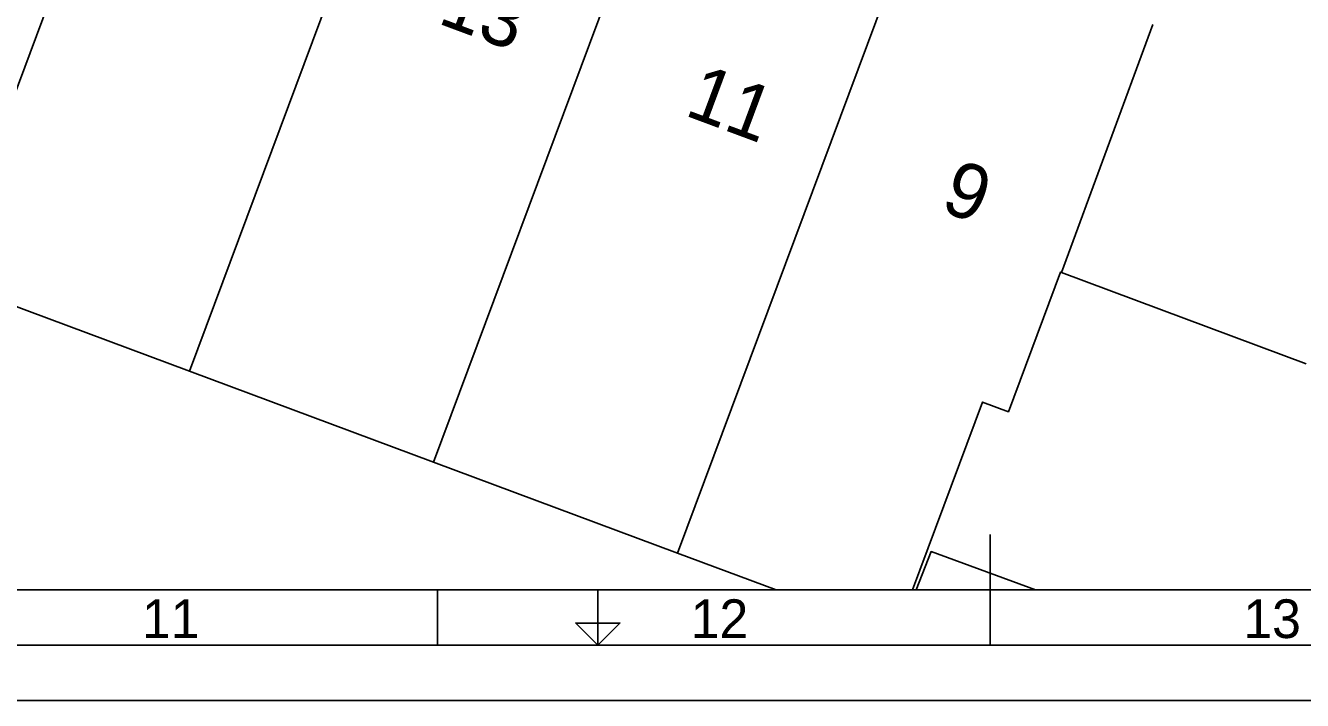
# Model space of a CAD drawing. Extents: x 192672 to 192910, y 446344 to 446512.
# Drawn here: x 192773.19 to 192796.29, y 446343.56 to 446355.77 of the extents above; entities that cross this region are included whole.
import ezdxf

# ---------------------------------------------------------------- set-up
doc = ezdxf.new("R2010")
doc.units = 0
for name, color, linetype in [('1010 viewport', 7, 'Continuous'), ('huisnummerreeks BGT', 7, 'Continuous'), ('pand op maaiveld vlak', 7, 'Continuous'), ('X-XX-AL-TEKENBLAD-S', 7, 'Continuous')]:
    doc.layers.add(name, color=color, linetype=linetype)

msp = doc.modelspace()

# ---------------------------------------------------------------- linework, layer by layer
at = {"layer": '1010 viewport'}
msp.add_lwpolyline([(192675.743, 446509.756), (192860.643, 446509.756), (192860.643, 446345.556), (192675.743, 446345.556)], close=True, dxfattribs=at)
at = {"layer": 'pand op maaiveld vlak'}
for p, q in [((192780.333, 446360.728), (192776.152, 446349.513)), ((192784.751, 446359.082), (192780.57, 446347.867)), ((192789.168, 446357.435), (192784.987, 446346.22)), ((192791.933, 446351.298), (192793.585, 446355.788)), ((192796.362, 446349.647), (192791.933, 446351.298)), ((192776.152, 446349.513), (192780.57, 446347.867)), ((192784.987, 446346.22), (192780.57, 446347.867)), ((192786.768, 446345.556), (192784.987, 446346.22))]:
    msp.add_line(p, q, dxfattribs=at)
for points in [[(192780.333, 446360.728), (192775.916, 446362.375), (192771.735, 446351.16), (192776.152, 446349.513)], [(192791.933, 446351.298), (192791.912, 446351.306), (192790.971, 446348.781), (192790.502, 446348.956), (192789.234, 446345.556)], [(192791.464, 446345.556), (192789.574, 446346.25), (192789.305, 446345.556)]]:
    msp.add_lwpolyline(points, dxfattribs=at)
at = {"layer": 'X-XX-AL-TEKENBLAD-S'}
for p, q in [((192780.643, 446344.556), (192780.643, 446345.556)), ((192783.543, 446345.556), (192783.543, 446344.556)), ((192783.543, 446344.956), (192783.543, 446344.556)), ((192783.543, 446344.556), (192783.543, 446344.956)), ((192674.743, 446344.556), (192908.543, 446344.556)), ((192671.743, 446343.556), (192909.543, 446343.556))]:
    msp.add_line(p, q, dxfattribs=at)
msp.add_lwpolyline([(192675.743, 446345.556), (192907.543, 446345.556), (192907.543, 446509.756), (192675.743, 446509.756)], close=True, dxfattribs=at)
for points in [[(192790.643, 446344.556), (192790.643, 446346.556)], [(192783.543, 446344.556), (192783.143, 446344.956), (192783.543, 446344.956)], [(192783.543, 446344.956), (192783.943, 446344.956), (192783.543, 446344.556)]]:
    msp.add_lwpolyline(points, dxfattribs=at)

# ---------------------------------------------------------------- texts
at = {"layer": 'huisnummerreeks BGT'}
for s, p in [('13', (192780.622, 446355.818)), ('11', (192785.088, 446354.153)), ('9', (192789.712, 446352.43))]:
    msp.add_text(s, height=1, rotation=339.6, dxfattribs=at).set_placement(p)
at = {"layer": 'X-XX-AL-TEKENBLAD-S'}
for s, p in [('11', (192775.293, 446344.685)), ('12', (192785.224, 446344.685)), ('13', (192795.223, 446344.685))]:
    msp.add_text(s, height=0.7, dxfattribs=at).set_placement(p)

doc.saveas('drawing.dxf')
